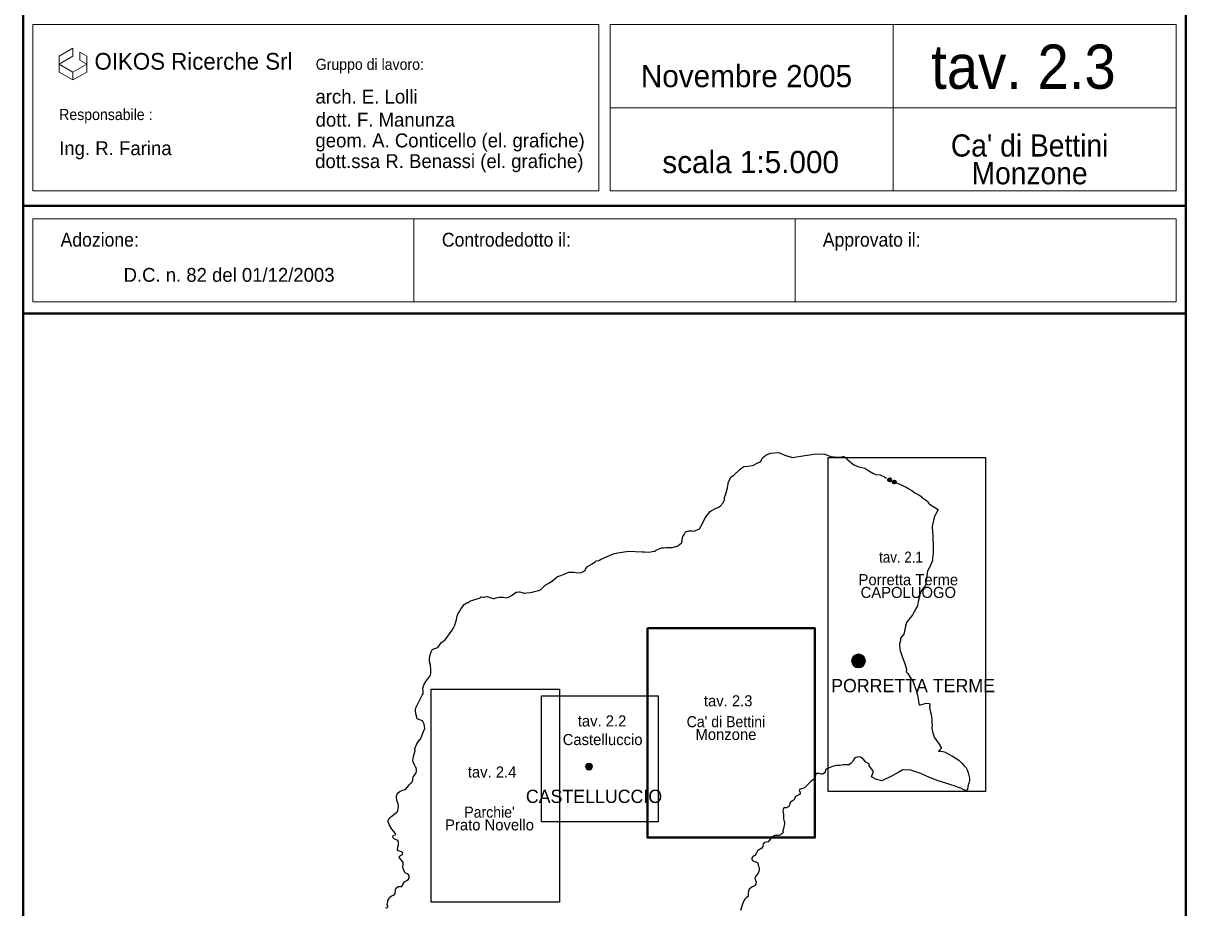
# Model space of a CAD drawing. Extents: x 652791 to 656927, y 889884 to 892405.
# Drawn here: x 652791 to 653841, y 890382 to 891181 of the extents above; entities that cross this region are included whole.
import ezdxf
from ezdxf.enums import TextEntityAlignment as Align

# ---------------------------------------------------------------- set-up
doc = ezdxf.new("R2010")
doc.units = 0
doc.header["$LTSCALE"] = 5.6
doc.header["$PDMODE"] = 32
doc.header["$PDSIZE"] = 2.8
doc.layers.add('61', color=7, linetype='Continuous', lineweight=35)

msp = doc.modelspace()

# ---------------------------------------------------------------- hatches: boundary and pattern name
at = {"layer": '61'}
for points in [[(653551.8, 890604.87, 1), (653539.08, 890604.87, 1)], [(653305.19, 890509.38, 1), (653298.83, 890509.38, 1)]]:
    msp.add_hatch(color=256, dxfattribs=at).paths.add_polyline_path(points)

# ---------------------------------------------------------------- linework, layer by layer
at = {"layer": '61', "lineweight": 13}
for p, q in [((652799.54, 891179.68), (652799.54, 891029.25)), ((652799.54, 891179.68), (653310.99, 891179.68)), ((653310.99, 891179.68), (653310.99, 891029.25)), ((653321.02, 891179.68), (653321.02, 891029.25)), ((653321.02, 891179.68), (653832.49, 891179.68)), ((653576.77, 891179.68), (653576.77, 891029.25)), ((653832.49, 891179.68), (653832.49, 891029.25)), ((653321.01, 891104.47), (653832.48, 891104.47)), ((652799.54, 891029.25), (653310.99, 891029.25)), ((653321.02, 891029.25), (653832.49, 891029.25)), ((652799.54, 891004.18), (652799.54, 890928.98)), ((652799.55, 891004.19), (653832.5, 891004.19)), ((653143.84, 891004.18), (653143.84, 890928.98)), ((653488.17, 891004.18), (653488.17, 890928.98)), ((653832.49, 891004.18), (653832.49, 890928.98)), ((652799.54, 890928.98), (653832.49, 890928.98))]:
    msp.add_line(p, q, dxfattribs=at)
at = {"layer": '61', "lineweight": 40}
for p, q in [((652791.02, 891015.72), (653841.02, 891015.72)), ((652791.02, 890918.43), (653841.02, 890918.43)), ((652791.02, 890918.43), (652791.02, 889884.41)), ((653841.02, 890918.43), (653841.02, 889884.41))]:
    msp.add_line(p, q, dxfattribs=at)
for points in [[(653841.02, 892404.68), (653841.02, 890918.43), (652791.02, 890918.43), (652791.02, 892404.68)], [(653354.79, 890634.35), (653506.11, 890634.35), (653506.11, 890445.33), (653354.79, 890445.33)]]:
    msp.add_lwpolyline(points, close=True, dxfattribs=at)
at = {"layer": '61', "lineweight": 13}
for points in [[(652835.93, 891158.13), (652823.51, 891150.99), (652823.51, 891143.82), (652835.93, 891150.99)], [(652848.34, 891150.99), (652842.13, 891154.56), (652842.13, 891147.41), (652848.34, 891143.82)], [(652835.93, 891136.66), (652823.51, 891143.82), (652823.51, 891136.66), (652835.93, 891129.52)], [(652848.34, 891143.82), (652835.93, 891136.66), (652835.93, 891129.52), (652848.34, 891136.66)]]:
    msp.add_lwpolyline(points, close=True, dxfattribs=at)
at = {"layer": '61', "lineweight": 25}
for points in [[(653423.31, 890747.55), (653424.53, 890750.63), (653424.29, 890752.26), (653425.31, 890754.74), (653425.83, 890756.75), (653426.97, 890761.19), (653427.57, 890764.67), (653427.57, 890765.71), (653428.95, 890768.26), (653430.43, 890771.03), (653432.85, 890772.59), (653438.15, 890777.62), (653439.93, 890779.22), (653441.79, 890780.38), (653445.59, 890780.83), (653449.35, 890781.43), (653450.53, 890781.66), (653453.91, 890783.38), (653457.23, 890784.82), (653458.05, 890786.99), (653458.83, 890788.1), (653460.33, 890789.38), (653461.81, 890790.54), (653463.65, 890791.43), (653466.15, 890792.31), (653469.49, 890792.66), (653473.47, 890792.95), (653476.91, 890791.51), (653478.81, 890790.66), (653480.57, 890789.94), (653485.71, 890788.54), (653497.11, 890790.23), (653507.07, 890791.87), (653515.09, 890791.42), (653520.39, 890789.47), (653523.73, 890789.22), (653528.55, 890788.86), (653531.19, 890789.42), (653532.15, 890789.35), (653533.05, 890788.95)], [(653533.05, 890788.95), (653533.95, 890788.34), (653535.27, 890787.1), (653537.51, 890784.99), (653539.23, 890783.3), (653541.51, 890781.82), (653545.71, 890780.11), (653551.11, 890778.99), (653554.71, 890776.58), (653558.25, 890774.42), (653560.71, 890773.27), (653564.97, 890772.98), (653569.05, 890771.07), (653570.69, 890769.9)], [(653577.79, 890766.39), (653582.73, 890764.59), (653586.33, 890762.7), (653588.43, 890761.67), (653590.83, 890760.23), (653593.65, 890758.62), (653596.35, 890756.75), (653599.89, 890754.91), (653601.81, 890753.47), (653603.35, 890751.78), (653605.83, 890750.27), (653607.21, 890749.51), (653607.75, 890748.67), (653608.91, 890746.99), (653609.43, 890746.47), (653611.01, 890745.46), (653617.47, 890741.71), (653614.89, 890737.03), (653614.05, 890735.18), (653613.35, 890733.07), (653612.07, 890726.11), (653612.13, 890721.11), (653612.45, 890718.67), (653612.61, 890713.55), (653612.77, 890711.67), (653612.99, 890709.26), (653612.97, 890702.15), (653612.55, 890699.74), (653612.39, 890698.5), (653612.33, 890697.1), (653612.13, 890695.34), (653611.97, 890694.82), (653610.39, 890691.31), (653608.31, 890686.63), (653607.89, 890686.55), (653607.15, 890681.27), (653606.85, 890679.7), (653606.65, 890677.42), (653606.21, 890675.18), (653605.89, 890673.19)], [(653325.03, 890701.78), (653327.95, 890702.3), (653337.65, 890703.83), (653350.03, 890703.46), (653352.07, 890703.31), (653356.47, 890703.1), (653358.97, 890703.55), (653360.45, 890703.95), (653361.77, 890704.02), (653362.59, 890704.71), (653365.35, 890705.98), (653367.95, 890706.83), (653369.31, 890707.07), (653371.83, 890707.14), (653375.15, 890707.14), (653376.99, 890707.14), (653380.51, 890708.15), (653382.29, 890708.63), (653383.89, 890710.03), (653385.87, 890711.51), (653386.23, 890714.27), (653386.89, 890717.23), (653387.83, 890719.07), (653388.63, 890720.14), (653389.29, 890721.35), (653392.19, 890722.39), (653395.05, 890722.15), (653397.13, 890722.1), (653398.27, 890722.67), (653401.71, 890723.99), (653403.21, 890726.78), (653405.35, 890730.82), (653406.95, 890733.98), (653408.97, 890736.82), (653411.47, 890739.87), (653412.25, 890740.43), (653415.69, 890742.07), (653418.85, 890743.75), (653420.51, 890744.5), (653423.31, 890747.55)], [(653227.23, 890661.74), (653229.81, 890662.74), (653232.17, 890663.78), (653234.15, 890665.34), (653236.19, 890666.87), (653237.07, 890666.95), (653238.81, 890667.23), (653239.45, 890667.19), (653243.39, 890666.07), (653244.03, 890666.07), (653245.77, 890666.34), (653249.07, 890666.58), (653250.81, 890666.95), (653252.85, 890667.5), (653256.41, 890668.5), (653258.19, 890669.03), (653262.39, 890673.26), (653266.29, 890675.23), (653269.35, 890677.39), (653273.61, 890680.99), (653276.43, 890681.87), (653279.61, 890683.22), (653283.87, 890685.07), (653284.57, 890685.11), (653288.39, 890684.95), (653291.65, 890684.39), (653295.09, 890684.7), (653297.07, 890685.62), (653298.73, 890686.99), (653298.67, 890687.47), (653299.43, 890688.59), (653300.59, 890690.02), (653304.79, 890692.43), (653307.87, 890694.59), (653308.09, 890695.14), (653310.81, 890695.5), (653312.31, 890696.27), (653318.55, 890698.99), (653324.21, 890701.5), (653325.03, 890701.78)], [(653605.89, 890673.19), (653605.69, 890672.5), (653604.75, 890671.51), (653603.75, 890670.43), (653603.11, 890669.55), (653602.37, 890668.5), (653601.37, 890666.19), (653600.83, 890664.83), (653600.13, 890661.9), (653599.45, 890658.46), (653598.71, 890654.78), (653598.45, 890653.98), (653597.91, 890653.07), (653595.65, 890649.06), (653594.07, 890646.34), (653592.71, 890644.35), (653590.61, 890641.82), (653589.71, 890640.7), (653588.69, 890639.47), (653587.93, 890636.06), (653586.91, 890631.71), (653586.27, 890629.1), (653584.75, 890627.26), (653583.33, 890625.34), (653583.33, 890624.95), (653583.27, 890623.27), (653582.71, 890621.18), (653582.45, 890620.19), (653582.57, 890619.26), (653582.83, 890615.86), (653583.09, 890613.94), (653583.59, 890612.51), (653584.55, 890609.79), (653586.15, 890605.39), (653587.29, 890602.62), (653588.83, 890597.1), (653588.83, 890596.34), (653588.57, 890595.1), (653589.99, 890593.31), (653591.77, 890590.58)], [(653178.45, 890632.55), (653180.07, 890635.34), (653180.83, 890637.07), (653181.71, 890639.98), (653182.29, 890642.23), (653183.05, 890645.19), (653183.99, 890647.5), (653185.09, 890649.47), (653186.61, 890652.07), (653187.69, 890653.63), (653189.25, 890655.86), (653191.91, 890657.47), (653193.07, 890657.71), (653194.09, 890658.34), (653195.11, 890659.07), (653197.17, 890659.7), (653201.95, 890661.19), (653203.17, 890661.55), (653203.67, 890661.91), (653204.49, 890662.55), (653205.15, 890662.55), (653206.33, 890662.3), (653207.03, 890662.3), (653208.31, 890662.74), (653210.43, 890662.87), (653211.39, 890662.55), (653212.53, 890662.06), (653214.13, 890661.55), (653215.35, 890661.31), (653216.43, 890661.31), (653218.09, 890661.67), (653219.49, 890662.06), (653221.03, 890662.43), (653222.23, 890662.5), (653223.01, 890662.5), (653224.59, 890662.3), (653226.07, 890662.18), (653227.23, 890661.74)], [(653153.25, 890547.7), (653152.23, 890549.5), (653151.61, 890550.55), (653148.41, 890551.78), (653146.89, 890552.63), (653146.23, 890555.31), (653145.61, 890556.98), (653145.27, 890560.31), (653145.53, 890562.31), (653145.93, 890563.18), (653151.35, 890573.83), (653152.31, 890575.07), (653152.35, 890575.9), (653152.23, 890577.14), (653151.91, 890580.06), (653152.49, 890582.23), (653153.07, 890583.95), (653154.79, 890586.23), (653157.27, 890589.71), (653158.87, 890591.63), (653159.25, 890593.99), (653159.01, 890597.39), (653158.75, 890600.87), (653158.05, 890604.39), (653157.97, 890606.51), (653158.35, 890609.11), (653159.07, 890612.15), (653160.09, 890614.58), (653160.59, 890615.02), (653162.01, 890615.75), (653164.61, 890616.55), (653165.43, 890617.06), (653166.39, 890618.23), (653167.47, 890619.83), (653168.69, 890621.46), (653170.23, 890622.51), (653172.01, 890623.94), (653174.43, 890627.15), (653176.17, 890629.39), (653178.45, 890632.55)], [(653591.77, 890590.58), (653594.69, 890585.87), (653595.71, 890583.22), (653597.57, 890578.51), (653598.59, 890573.82), (653599.73, 890568.54), (653600.31, 890564.87), (653601.45, 890565.23), (653605.59, 890566.23), (653607.65, 890566.62), (653609.43, 890566.5), (653609.87, 890564.31), (653609.69, 890563.39), (653609.55, 890562.83), (653610.01, 890561.15), (653610.57, 890558.63), (653611.03, 890556.39), (653611.29, 890554.42), (653611.53, 890551.94), (653611.79, 890548.54), (653611.99, 890547.55), (653611.67, 890543.63), (653611.85, 890542.31), (653612.31, 890541.58), (653612.25, 890541.02), (653613.83, 890536.07), (653618.25, 890529.75), (653620.47, 890526.06), (653617.83, 890523.31), (653619.25, 890523.26), (653620.25, 890523.35), (653621.61, 890523.03), (653623.65, 890522.34), (653625.91, 890521.31), (653630.25, 890518.9), (653632.85, 890517.27), (653635.99, 890515.11), (653638.91, 890512.51), (653640.89, 890510.19), (653642.55, 890508.27)], [(653129.83, 890473.99), (653129.51, 890475.47), (653128.55, 890479.07), (653128.17, 890481.67), (653128.23, 890482.54), (653128.87, 890484.59), (653129.77, 890485.63), (653131.43, 890487.07), (653134.75, 890488.43), (653136.59, 890489.11), (653139.03, 890492.07), (653139.73, 890492.83), (653140.17, 890493.5), (653141.39, 890494.75), (653142.27, 890495.18), (653142.41, 890495.99), (653142.79, 890496.98), (653142.93, 890498.47), (653143.17, 890499.83), (653144.39, 890501.55), (653145.81, 890503.86), (653146.11, 890505.54), (653146.11, 890506.75), (653145.81, 890508.11), (653145.29, 890509.11), (653144.39, 890510.99), (653143.11, 890513.78), (653142.99, 890514.9), (653143.49, 890518.5), (653144.45, 890521.95), (653144.91, 890523.63), (653144.85, 890525.62), (653146.49, 890529.83), (653147.65, 890531.7), (653148.93, 890533.62), (653149.69, 890534.27), (653150.97, 890537.14), (653152.63, 890541.03), (653153.85, 890543.71), (653153.25, 890547.7)], [(653542.25, 890517.23), (653540.55, 890514.91), (653540.01, 890513.59), (653538.87, 890512.55), (653537.09, 890510.95), (653536.07, 890510.9), (653532.83, 890510.98), (653531.67, 890510.9), (653528.89, 890510.51), (653525.29, 890510.23), (653522.01, 890509.58), (653519.03, 890508.39), (653515.63, 890506.63), (653515.23, 890503.99), (653513.05, 890502.39), (653512.11, 890502.59), (653509.59, 890503.14), (653507.19, 890503.19), (653506.33, 890500.82), (653504.69, 890497.71), (653501.77, 890495.27), (653499.05, 890492.59), (653496.53, 890490.27), (653493.87, 890489.15), (653492.21, 890488.58), (653491.95, 890487.54), (653492.43, 890486.74), (653492.75, 890485.15), (653492.15, 890484.1), (653490.25, 890483.31), (653488.47, 890482.51), (653487.99, 890481.59), (653487.59, 890479.82), (653486.35, 890478.71), (653484.83, 890477.82), (653483.97, 890477.15), (653483.43, 890476.26), (653483.13, 890474.39), (653482.45, 890473.31), (653481.71, 890472.66)], [(653642.55, 890508.27), (653643.45, 890506.3), (653644.47, 890503.63), (653645.73, 890498.79), (653645.61, 890496.74), (653644.99, 890494.38), (653644.31, 890491.31), (653644.03, 890488.5), (653642.01, 890487.91), (653640.09, 890488.55), (653637.79, 890490.02), (653634.73, 890490.79), (653632.01, 890491.87), (653629.83, 890492.51), (653627.05, 890493.63), (653624.25, 890494.38), (653617.47, 890496.55), (653609.57, 890499.58), (653601.69, 890503.03), (653592.57, 890506.27), (653585.49, 890506.39), (653581.97, 890504.42), (653575.71, 890501.14), (653566.61, 890496.43), (653561.73, 890497.78), (653557.17, 890500.03), (653558.27, 890503.43), (653558.95, 890504.9), (653557.53, 890506.99), (653555.89, 890508.98), (653555.07, 890510.43), (653555.07, 890511.75), (653554.73, 890511.9), (653552.15, 890513.47), (653550.19, 890515.58), (653548.55, 890516.9), (653547.19, 890517.95), (653545.83, 890518.15), (653544.37, 890517.9), (653542.25, 890517.23)], [(653137.17, 890412.79), (653135.97, 890413.15), (653135.07, 890415.22), (653134.11, 890417.43), (653133.79, 890419.23), (653134.23, 890421.35), (653134.23, 890422.83), (653132.71, 890424.94), (653130.79, 890426.91), (653130.61, 890427.98), (653131.69, 890428.98), (653133.47, 890430.02), (653133.93, 890431.31), (653133.35, 890432.19), (653131.17, 890432.87), (653129.57, 890433.23), (653129.13, 890434.23), (653129.39, 890436.83), (653130.03, 890438.27), (653129.91, 890441.02), (653129.25, 890442.62), (653128.11, 890443.23), (653126.33, 890443.74), (653125.17, 890444.98), (653124.79, 890446.22), (653125.55, 890447.34), (653127.15, 890447.87), (653127.67, 890448.31), (653127.21, 890449.07), (653123.97, 890452.91), (653121.73, 890456.38), (653120.65, 890459.35), (653120.65, 890460.78), (653121.33, 890462.15), (653122.73, 890463.83), (653125.61, 890466.11), (653128.35, 890468.35), (653129.43, 890469.23), (653129.77, 890471.63), (653129.83, 890473.99)], [(653481.71, 890472.66), (653480.31, 890472.27), (653478.79, 890472.23), (653478.11, 890472.03), (653477.37, 890470.95), (653476.99, 890469.71), (653477.27, 890467.91), (653477.73, 890465.94), (653477.79, 890464.35), (653477.79, 890462.27), (653477.93, 890461.03), (653478.27, 890459.99), (653478.57, 890459.02), (653478.57, 890457.74), (653478.41, 890456.31), (653477.83, 890453.47), (653477.19, 890451.31), (653477.25, 890449.87), (653476.57, 890448.94), (653474.99, 890447.79), (653473.53, 890447.1), (653472.41, 890447.23), (653470.07, 890447.23), (653469.25, 890446.9), (653467.19, 890445.3), (653465.97, 890444.19), (653463.93, 890441.27), (653460.71, 890440.9), (653459.19, 890439.62), (653459.15, 890437.3), (653458.23, 890435.7), (653456.61, 890434.83), (653455.11, 890433.98), (653454.23, 890433.22), (653453.17, 890431.42), (653451.89, 890429.15), (653451.07, 890428.67), (653449.99, 890427.95), (653449.41, 890427.22), (653449.17, 890426.35)], [(653449.17, 890426.35), (653449.21, 890425.46), (653449.95, 890424.23), (653450.77, 890423.95), (653452.83, 890423.38), (653454.57, 890422.58), (653454.77, 890421.02), (653454.81, 890420.06), (653455.35, 890418.9), (653455.65, 890417.75), (653455.65, 890416.86), (653455.31, 890414.63), (653454.67, 890413.26), (653453.45, 890411.46), (653452.33, 890409.67), (653451.93, 890408.47), (653451.99, 890407.3), (653452.39, 890406.23), (653452.99, 890405.22), (653452.79, 890403.11), (653451.91, 890401.9), (653451.09, 890401.42), (653449.29, 890400.79), (653447.91, 890399.71), (653446.79, 890398.54), (653446.11, 890397.31), (653445.67, 890394.74), (653445.77, 890392.19), (653444.35, 890391.19), (653442.89, 890389.59), (653442.11, 890388.66), (653440.69, 890384.99), (653438.73, 890379.27)], [(653118.29, 890381.86), (653119.59, 890382.22), (653120.19, 890382.59), (653120.31, 890383.07), (653120.13, 890383.95), (653119.83, 890384.95), (653119.99, 890386.1), (653120.37, 890387.59), (653120.43, 890388.58), (653120.79, 890389.42), (653121.99, 890391.31), (653123.37, 890392.43), (653124.39, 890392.91), (653125.77, 890393.26), (653126.43, 890393.87), (653126.85, 890394.79), (653127.09, 890395.74), (653127.25, 890396.86), (653127.33, 890398.31), (653127.63, 890398.99), (653128.05, 890399.86), (653128.91, 890400.55), (653129.77, 890401.07), (653131.01, 890401.1), (653132.49, 890401.22), (653133.15, 890401.67), (653133.87, 890402.51), (653134.21, 890403.46), (653135.31, 890405.15), (653137.35, 890406.43), (653138.71, 890407.27), (653139.47, 890408.51), (653139.61, 890410.79), (653138.53, 890412.47), (653137.17, 890412.79)]]:
    msp.add_lwpolyline(points, dxfattribs=at)
for points in [[(653517.97, 890788.42), (653660.06, 890788.42), (653660.06, 890486.89), (653517.97, 890486.89)], [(653275.49, 890579.42), (653275.49, 890386.99), (653159.39, 890386.99), (653159.39, 890579.42)], [(653259.07, 890573.34), (653364.59, 890573.34), (653364.59, 890459.48), (653259.07, 890459.48)]]:
    msp.add_lwpolyline(points, close=True, dxfattribs=at)
at = {"layer": '61', "lineweight": 13}
for centre, radius in [((653545.44, 890604.87), 6.36), ((653302.01, 890509.38), 3.18)]:
    msp.add_circle(centre, radius, dxfattribs=at)
at = {"layer": '61'}
for p in [(653573.61, 890768.39), (653577.79, 890766.39)]:
    msp.add_point(p, dxfattribs=at)

# ---------------------------------------------------------------- texts
for s, height, width, p in [('tav. 2.3', 40, 0.95, (653611.11, 891121.48)), ('Gruppo di lavoro:', 10.03, 0.95, (653055.16, 891138.63)), ('Responsabile :', 10.03, 0.95, (652823.44, 891093.28)), ('Adozione:', 12.5, 0.95, (652824.76, 890978.98)), ('Controdedotto il:', 12.5, 0.95, (653169.14, 890978.98)), ('Approvato il:', 12.5, 0.95, (653513.21, 890978.98)), ('tav. 2.1', 10, 0.9, (653564.08, 890693.56))]:
    msp.add_text(s, height=height, dxfattribs=dict(at, width=width)).set_placement(p)
for s, height, p in [('OIKOS Ricerche Srl', 15.04, (652855.36, 891138.81)), ('arch. E. Lolli', 12.54, (653054.94, 891108.21)), ('dott. F. Manunza', 12.54, (653055.11, 891087.33)), ('Ing. R. Farina', 12.54, (652823.46, 891061.58)), ('geom. A. Conticello (el. grafiche)', 12.54, (653054.89, 891068.63)), ('dott.ssa R. Benassi (el. grafiche)', 12.54, (653054.66, 891049.93)), ('scala 1:5.000     ', 20.06, (653368.26, 891045.36)), ('D.C. n. 82 del 01/12/2003', 12.5, (652881.66, 890947.2)), ('tav. 2.3', 10, (653405.82, 890563.79)), ('tav. 2.2', 10, (653291.88, 890545.61)), ('tav. 2.4', 10, (653192.56, 890499.51))]:
    msp.add_text(s, height=height, dxfattribs=at).set_placement(p)
for s, height, p in [('Novembre 2005', 20.06, (653444.26, 891122.98)), ('Porretta Terme', 10, (653590.45, 890673.18)), ('CAPOLUOGO', 10, (653590.44, 890661.68)), ('PORRETTA TERME', 12, (653594.73, 890576.51)), ('Castelluccio', 10, (653314.31, 890528.8)), ('Monzone', 10, (653425.71, 890533.42)), ('CASTELLUCCIO', 12, (653306.54, 890476.5)), ('Prato Novello', 10, (653212.16, 890451.75))]:
    msp.add_text(s, height=height, dxfattribs=at).set_placement(p, align=Align.CENTER)
at = {"layer": '61', "width": 0.95}
for s, height, p in [("Ca' di Bettini", 20.06, (653700, 891060.31)), ('Monzone', 20.06, (653699.97, 891035.26)), ("Ca' di Bettini", 10, (653425.71, 890544.92)), ("Parchie'", 10, (653212.16, 890463.25))]:
    msp.add_text(s, height=height, dxfattribs=at).set_placement(p, align=Align.CENTER)

doc.saveas('drawing.dxf')
